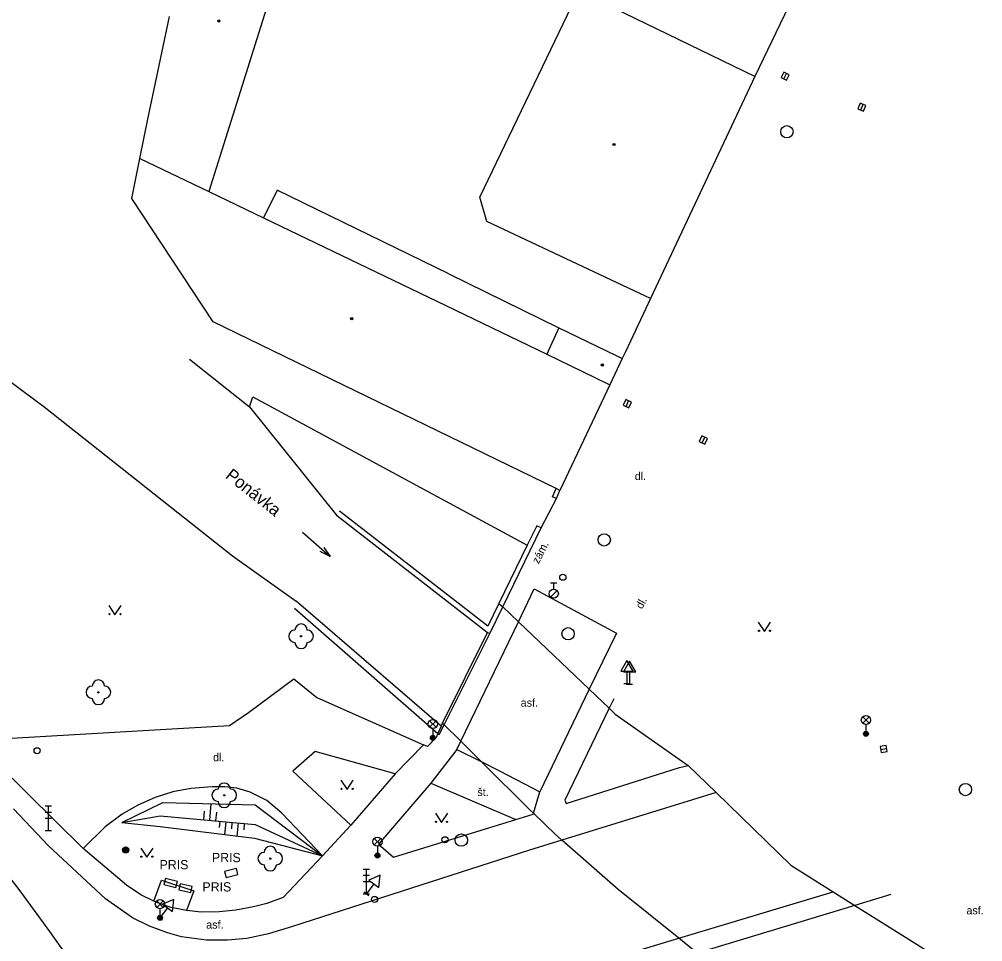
# Model space of a CAD drawing. Extents: x -598341 to -594502, y -1162301 to -1161406.
# Drawn here: x -597440.9 to -597362.6, y -1161701 to -1161626.1 of the extents above; entities that cross this region are included whole.
import ezdxf

# ---------------------------------------------------------------- set-up
doc = ezdxf.new("R2010")
doc.units = 0
for name, color, linetype in [('Vrstva 10', 7, 'Continuous'), ('Vrstva 11', 7, 'Continuous'), ('Vrstva 13', 7, 'Continuous'), ('Vrstva 14', 7, 'Continuous'), ('Vrstva 15', 7, 'Continuous'), ('Vrstva 22', 7, 'Continuous'), ('Vrstva 24', 7, 'Continuous'), ('Vrstva 25', 7, 'Continuous'), ('Vrstva 27', 7, 'Continuous'), ('Vrstva 28', 7, 'Continuous'), ('Vrstva 33', 7, 'Continuous'), ('Vrstva 34', 7, 'Continuous'), ('Vrstva 36', 7, 'Continuous'), ('Vrstva 39', 7, 'Continuous'), ('Vrstva 40', 7, 'Continuous'), ('Vrstva 41', 7, 'Continuous'), ('Vrstva 45', 7, 'Continuous'), ('Vrstva 5', 7, 'Continuous'), ('Vrstva 7', 7, 'Continuous'), ('Vrstva 8', 7, 'Continuous'), ('Vrstva 9', 7, 'Continuous')]:
    doc.layers.add(name, color=color, linetype=linetype)

msp = doc.modelspace()

# ---------------------------------------------------------------- linework, layer by layer
at = {"layer": 'Vrstva 10'}
for p, q in [((-597370.1, -1161697.18), (-597373.02, -1161698.07)), ((-597373.02, -1161698.07), (-597385.82, -1161701.94)), ((-597418.7, -1161699.79), (-597420.65, -1161700.39))]:
    msp.add_line(p, q, dxfattribs=at)
for points in [[(-597400.35, -1161675.03), (-597399.06, -1161672.36)], [(-597405.03, -1161684.74), (-597400.35, -1161675.03)], [(-597392.38, -1161675.96), (-597394.59, -1161680.52)], [(-597394.59, -1161680.52), (-597398.61, -1161688.85)], [(-597405.35, -1161685.4), (-597405.03, -1161684.74)], [(-597405.35, -1161685.4), (-597403.37, -1161686.39)], [(-597403.37, -1161686.39), (-597401.88, -1161687.13), (-597398.61, -1161688.85)], [(-597384.3, -1161688.91), (-597386.21, -1161689.5), (-597396.81, -1161692.78)], [(-597441.35, -1161690.23), (-597438.49, -1161693.23), (-597433.86, -1161697.55)], [(-597396.81, -1161692.78), (-597399.44, -1161693.59), (-597418.7, -1161699.79)], [(-597420.65, -1161700.39), (-597422.4, -1161700.77), (-597423.96, -1161700.91), (-597425.66, -1161700.91), (-597427.69, -1161700.63), (-597428.84, -1161700.31), (-597430.29, -1161699.77), (-597431.69, -1161699.07), (-597433.86, -1161697.55)], [(-597387.31, -1161700.74), (-597374.78, -1161696.97)], [(-597405.85, -1161708), (-597406.33, -1161706.48), (-597387.31, -1161700.74)]]:
    msp.add_lwpolyline(points, dxfattribs=at)
at = {"layer": 'Vrstva 11'}
for p, q in [((-597405.99, -1161646.77), (-597397.06, -1161651.14)), ((-597422.18, -1161657.58), (-597421.9, -1161656.76)), ((-597421.9, -1161656.76), (-597399.63, -1161668.81)), ((-597397.26, -1161665.03), (-597396.98, -1161664.36)), ((-597415.12, -1161666.36), (-597402.85, -1161675.89)), ((-597401.61, -1161673.83), (-597398.5, -1161667.41)), ((-597399.06, -1161672.36), (-597392.38, -1161675.96)), ((-597406.61, -1161683.5), (-597418.38, -1161673.35)), ((-597440.21, -1161688.98), (-597444.66, -1161684.59)), ((-597410.34, -1161687.39), (-597413.95, -1161691.56)), ((-597407.47, -1161688.13), (-597400.55, -1161691.1)), ((-597435.68, -1161693.45), (-597440.21, -1161688.98)), ((-597419.55, -1161690.59), (-597416.26, -1161694.05)), ((-597435.68, -1161693.45), (-597433.91, -1161691.68)), ((-597413.95, -1161691.56), (-597416.26, -1161694.05)), ((-597432.16, -1161696.43), (-597435.68, -1161693.45)), ((-597416.26, -1161694.05), (-597419.44, -1161697.43)), ((-597426.7, -1161696.9), (-597427.29, -1161698.5))]:
    msp.add_line(p, q, dxfattribs=at)
for points in [[(-597405.99, -1161646.77), (-597419.92, -1161639.96), (-597421.03, -1161642.23)], [(-597401.93, -1161673.54), (-597402.83, -1161675.4), (-597414.88, -1161666.04)], [(-597402.67, -1161675.99), (-597401.61, -1161673.83)], [(-597406.51, -1161683.28), (-597402.85, -1161675.89)], [(-597402.85, -1161675.89), (-597402.67, -1161675.99)], [(-597422.25, -1161682.39), (-597418.57, -1161679.66), (-597416.71, -1161681.18), (-597408.06, -1161685.03)], [(-597392.61, -1161681.3), (-597392.98, -1161682.06)], [(-597423.81, -1161683.45), (-597422.25, -1161682.39)], [(-597392.98, -1161682.06), (-597396.58, -1161689.53), (-597396.48, -1161689.79), (-597387.28, -1161686.86), (-597386.56, -1161686.72)], [(-597441.95, -1161684.52), (-597430.36, -1161683.83), (-597423.81, -1161683.45)], [(-597406.61, -1161683.5), (-597406.88, -1161684.1)], [(-597406.61, -1161683.5), (-597406.51, -1161683.28)], [(-597406.88, -1161684.1), (-597407.03, -1161684.44), (-597407.72, -1161685.16)], [(-597408.06, -1161685.03), (-597410.34, -1161687.39)], [(-597407.72, -1161685.16), (-597408.06, -1161685.03)], [(-597410.34, -1161687.39), (-597416.85, -1161685.57), (-597418.65, -1161687.16), (-597413.95, -1161691.56)], [(-597405.35, -1161685.4), (-597407.47, -1161688.13)], [(-597407.47, -1161688.13), (-597411.7, -1161693.09), (-597410.49, -1161694.16), (-597400.55, -1161691.1)], [(-597419.55, -1161690.59), (-597420.77, -1161689.56), (-597422.13, -1161688.88), (-597423.22, -1161688.56), (-597424.19, -1161688.44), (-597425.2, -1161688.45), (-597426.94, -1161688.58), (-597428.4, -1161688.86), (-597429.83, -1161689.32), (-597431.25, -1161689.92), (-597432.52, -1161690.65), (-597433.91, -1161691.68)], [(-597399.12, -1161690.59), (-597398.61, -1161688.85)], [(-597400.55, -1161691.1), (-597399.14, -1161690.67), (-597399.12, -1161690.59)], [(-597429.95, -1161697.73), (-597429.32, -1161696.01), (-597426.7, -1161696.9)], [(-597429.95, -1161697.73), (-597431, -1161697.21), (-597432.16, -1161696.43)], [(-597419.44, -1161697.43), (-597420.78, -1161697.92), (-597421.86, -1161698.2), (-597423.3, -1161698.47), (-597424.65, -1161698.6), (-597426.11, -1161698.61), (-597427.29, -1161698.5)], [(-597427.29, -1161698.5), (-597428.55, -1161698.24), (-597429.48, -1161697.92), (-597429.95, -1161697.73)]]:
    msp.add_lwpolyline(points, dxfattribs=at)
at = {"layer": 'Vrstva 13'}
msp.add_lwpolyline([(-597470.38, -1161668.8), (-597467.36, -1161670.94), (-597464.35, -1161673.04), (-597461.12, -1161675.62), (-597458.26, -1161678.06), (-597455.83, -1161680.23), (-597452.69, -1161683.22), (-597449.69, -1161686.37), (-597447.17, -1161689.18), (-597444.05, -1161692.84), (-597441, -1161696.66), (-597438.41, -1161700.18), (-597435.66, -1161704.08), (-597430.7, -1161711.73), (-597427.13, -1161717.6), (-597424.11, -1161722.82), (-597422.33, -1161726)], dxfattribs=at)
at = {"layer": 'Vrstva 14'}
for p, q in [((-597401.61, -1161673.83), (-597400.35, -1161675.03)), ((-597400.35, -1161675.03), (-597394.59, -1161680.52)), ((-597394.59, -1161680.52), (-597392.98, -1161682.06)), ((-597392.98, -1161682.06), (-597392.48, -1161682.53)), ((-597392.48, -1161682.53), (-597386.56, -1161686.72)), ((-597406.38, -1161683.41), (-597406.51, -1161683.28)), ((-597405.03, -1161684.74), (-597406.38, -1161683.41)), ((-597403.37, -1161686.39), (-597405.03, -1161684.74)), ((-597399.37, -1161690.35), (-597403.37, -1161686.39)), ((-597368.92, -1161700.64), (-597365, -1161703.1))]:
    msp.add_line(p, q, dxfattribs=at)
for points in [[(-597427.04, -1161653.7), (-597422.18, -1161657.58)], [(-597443.15, -1161654.38), (-597439.28, -1161657.25)], [(-597439.28, -1161657.25), (-597438.87, -1161657.55), (-597423.56, -1161669.67), (-597418.38, -1161673.35)], [(-597422.18, -1161657.58), (-597415.12, -1161666.36)], [(-597386.56, -1161686.72), (-597384.3, -1161688.91)], [(-597384.3, -1161688.91), (-597378.23, -1161694.8), (-597374.78, -1161696.97)], [(-597432.55, -1161691.35), (-597429.21, -1161689.71), (-597421.73, -1161689.9)], [(-597421.73, -1161689.9), (-597416.26, -1161694.05)], [(-597399.12, -1161690.59), (-597399.37, -1161690.35)], [(-597396.81, -1161692.78), (-597397.36, -1161692.29), (-597399.12, -1161690.59)], [(-597432.55, -1161691.35), (-597429.42, -1161690.79), (-597421.71, -1161691.5)], [(-597432.55, -1161691.35), (-597429.43, -1161691.66), (-597421.77, -1161692.62)], [(-597421.71, -1161691.5), (-597416.26, -1161694.05)], [(-597421.77, -1161692.62), (-597416.26, -1161694.05)], [(-597387.31, -1161700.74), (-597392.25, -1161696.79), (-597396.81, -1161692.78)], [(-597374.78, -1161696.97), (-597373.02, -1161698.07)], [(-597373.02, -1161698.07), (-597368.92, -1161700.64)], [(-597385.82, -1161701.94), (-597387.31, -1161700.74)]]:
    msp.add_lwpolyline(points, dxfattribs=at)
at = {"layer": 'Vrstva 15'}
for p, q in [((-597425.41, -1161691.16), (-597425.28, -1161689.81)), ((-597425.9, -1161691.11), (-597425.84, -1161690.42)), ((-597424.91, -1161691.2), (-597424.84, -1161690.51)), ((-597424.6, -1161691.23), (-597424.64, -1161691.74)), ((-597424.1, -1161691.28), (-597424.2, -1161692.32)), ((-597423.6, -1161691.33), (-597423.65, -1161691.85)), ((-597423.1, -1161691.37), (-597423.2, -1161692.44)), ((-597422.61, -1161691.42), (-597422.65, -1161691.94))]:
    msp.add_line(p, q, dxfattribs=at)
at = {"layer": 'Vrstva 22'}
for centre in [(-597417.99, -1161676.21), (-597434.45, -1161680.76), (-597424.23, -1161689.13), (-597420.49, -1161694.27)]:
    msp.add_circle(centre, 0.05, dxfattribs=at)
for centre, start, end in [((-597418.49, -1161676.21), 90, 270), ((-597417.99, -1161675.71), 0, 180), ((-597417.49, -1161676.21), 270, 90), ((-597417.99, -1161676.71), 180, 0), ((-597434.95, -1161680.76), 90, 270), ((-597434.45, -1161680.26), 0, 180), ((-597433.95, -1161680.76), 270, 90), ((-597434.45, -1161681.26), 180, 0), ((-597424.23, -1161688.63), 0, 180), ((-597424.73, -1161689.13), 90, 270), ((-597423.73, -1161689.13), 270, 90), ((-597424.23, -1161689.63), 180, 0), ((-597420.49, -1161693.77), 0, 180), ((-597420.99, -1161694.27), 90, 270), ((-597419.99, -1161694.27), 270, 90), ((-597420.49, -1161694.77), 180, 0)]:
    msp.add_arc(centre, 0.5, start, end, dxfattribs=at)
at = {"layer": 'Vrstva 24'}
for points in [[(-597424.078, -1161695.811), (-597423.113, -1161695.552), (-597423.242, -1161695.069), (-597424.208, -1161695.328)], [(-597429.125, -1161696.386), (-597428.153, -1161696.621), (-597428.036, -1161696.135), (-597429.008, -1161695.9)], [(-597427.925, -1161696.796), (-597426.953, -1161697.031), (-597426.836, -1161696.545), (-597427.808, -1161696.31)]]:
    msp.add_lwpolyline(points, close=True, dxfattribs=at)
at = {"layer": 'Vrstva 25'}
for radius in [0.25, 0.2, 0.15, 0.1, 0.05]:
    msp.add_circle((-597432.23, -1161693.56), radius, dxfattribs=at)
at = {"layer": 'Vrstva 27'}
for p, q in [((-597378.798, -1161630.935), (-597378.582, -1161630.485)), ((-597372.555, -1161633.451), (-597372.365, -1161632.989)), ((-597391.605, -1161657.547), (-597391.395, -1161657.093)), ((-597385.438, -1161660.486), (-597385.222, -1161660.034)), ((-597370.936, -1161685.412), (-597370.443, -1161685.328))]:
    msp.add_line(p, q, dxfattribs=at)
for points in [[(-597378.573, -1161631.044), (-597378.356, -1161630.593), (-597378.807, -1161630.376), (-597379.024, -1161630.827)], [(-597372.324, -1161633.547), (-597372.133, -1161633.084), (-597372.596, -1161632.893), (-597372.787, -1161633.356)], [(-597391.378, -1161657.652), (-597391.168, -1161657.198), (-597391.622, -1161656.988), (-597391.832, -1161657.442)], [(-597385.212, -1161660.593), (-597384.997, -1161660.142), (-597385.448, -1161659.927), (-597385.663, -1161660.378)], [(-597370.894, -1161685.659), (-597370.401, -1161685.575), (-597370.485, -1161685.082), (-597370.978, -1161685.166)]]:
    msp.add_lwpolyline(points, close=True, dxfattribs=at)
for centre in [(-597378.55, -1161635.22), (-597393.38, -1161668.38), (-597396.31, -1161676.01), (-597364.05, -1161688.66), (-597404.98, -1161692.77)]:
    msp.add_circle(centre, 0.5, dxfattribs=at)
at = {"layer": 'Vrstva 28'}
for p, q in [((-597397.738, -1161673.022), (-597397.208, -1161672.492)), ((-597397.73, -1161671.875), (-597397.23, -1161671.875)), ((-597397.48, -1161672.375), (-597397.48, -1161671.875))]:
    msp.add_line(p, q, dxfattribs=at)
for centre, radius in [((-597396.74, -1161671.41), 0.25), ((-597397.48, -1161672.75), 0.375), ((-597439.42, -1161685.51), 0.25), ((-597406.31, -1161692.74), 0.25), ((-597412.03, -1161697.59), 0.25)]:
    msp.add_circle(centre, radius, dxfattribs=at)
at = {"layer": 'Vrstva 33'}
for p, q in [((-597372.395, -1161683.28), (-597371.865, -1161682.75)), ((-597372.395, -1161682.75), (-597371.865, -1161683.28)), ((-597407.555, -1161683.6), (-597407.025, -1161683.07)), ((-597407.555, -1161683.07), (-597407.025, -1161683.6)), ((-597372.13, -1161683.39), (-597372.13, -1161684.14)), ((-597407.29, -1161683.71), (-597407.29, -1161684.46)), ((-597438.76, -1161689.99), (-597438.26, -1161689.99)), ((-597438.76, -1161690.49), (-597438.26, -1161690.49)), ((-597438.51, -1161691.99), (-597438.51, -1161689.99)), ((-597438.76, -1161690.99), (-597438.26, -1161690.99)), ((-597438.76, -1161691.99), (-597438.26, -1161691.99)), ((-597412.055, -1161693.16), (-597411.525, -1161692.63)), ((-597412.055, -1161692.63), (-597411.525, -1161693.16)), ((-597411.79, -1161693.27), (-597411.79, -1161694.02)), ((-597412.94, -1161695.13), (-597412.44, -1161695.13)), ((-597412.69, -1161697.13), (-597412.69, -1161695.13)), ((-597412.94, -1161695.63), (-597412.44, -1161695.63)), ((-597412.94, -1161696.13), (-597412.44, -1161696.13)), ((-597412.94, -1161697.13), (-597412.44, -1161697.13)), ((-597429.715, -1161698.23), (-597429.185, -1161697.7)), ((-597429.715, -1161697.7), (-597429.185, -1161698.23)), ((-597429.45, -1161698.34), (-597429.45, -1161699.09))]:
    msp.add_line(p, q, dxfattribs=at)
for centre, radius in [((-597372.13, -1161683.015), 0.375), ((-597407.29, -1161683.335), 0.375), ((-597407.29, -1161684.46), 0.2), ((-597407.29, -1161684.46), 0.145), ((-597372.13, -1161684.14), 0.2), ((-597372.13, -1161684.14), 0.145), ((-597372.13, -1161684.14), 0.0876), ((-597407.29, -1161684.46), 0.0876), ((-597411.79, -1161692.895), 0.375), ((-597411.79, -1161694.02), 0.2), ((-597411.79, -1161694.02), 0.145), ((-597411.79, -1161694.02), 0.0876), ((-597429.45, -1161697.965), 0.375), ((-597429.45, -1161699.09), 0.2), ((-597429.45, -1161699.09), 0.145), ((-597429.45, -1161699.09), 0.0876)]:
    msp.add_circle(centre, radius, dxfattribs=at)
at = {"layer": 'Vrstva 34'}
for p, q in [((-597391.54, -1161679.032), (-597391.54, -1161680.05)), ((-597391.32, -1161679.092), (-597391.32, -1161680.11)), ((-597391.79, -1161680.05), (-597391.29, -1161680.05)), ((-597391.57, -1161680.11), (-597391.07, -1161680.11)), ((-597412.078, -1161696.317), (-597412.69, -1161697.13)), ((-597412.89, -1161696.98), (-597412.49, -1161697.28)), ((-597428.838, -1161698.277), (-597429.45, -1161699.09)), ((-597429.65, -1161698.94), (-597429.25, -1161699.24))]:
    msp.add_line(p, q, dxfattribs=at)
for points in [[(-597392.04, -1161679.032), (-597391.04, -1161679.032), (-597391.54, -1161678.166)], [(-597391.82, -1161679.092), (-597390.82, -1161679.092), (-597391.32, -1161678.226)], [(-597412.477, -1161696.016), (-597411.678, -1161696.617), (-597411.557, -1161695.625)], [(-597429.237, -1161697.976), (-597428.438, -1161698.577), (-597428.317, -1161697.585)]]:
    msp.add_lwpolyline(points, close=True, dxfattribs=at)
at = {"layer": 'Vrstva 36'}
for points in [[(-597433.6, -1161673.71), (-597433.1, -1161674.46), (-597432.6, -1161673.71)], [(-597380.87, -1161675.06), (-597380.37, -1161675.81), (-597379.87, -1161675.06)], [(-597414.76, -1161687.9), (-597414.26, -1161688.65), (-597413.76, -1161687.9)], [(-597407.09, -1161690.58), (-597406.59, -1161691.33), (-597406.09, -1161690.58)], [(-597431.01, -1161693.41), (-597430.51, -1161694.16), (-597430.01, -1161693.41)]]:
    msp.add_lwpolyline(points, dxfattribs=at)
for centre in [(-597433.55, -1161674.41), (-597432.651, -1161674.41), (-597380.82, -1161675.76), (-597379.921, -1161675.76), (-597414.71, -1161688.6), (-597413.811, -1161688.6), (-597407.04, -1161691.28), (-597406.141, -1161691.28), (-597430.96, -1161694.11), (-597430.061, -1161694.11)]:
    msp.add_circle(centre, 0.05, dxfattribs=at)
at = {"layer": 'Vrstva 39'}
for centre, radius in [((-597424.67, -1161626.22), 0.09), ((-597424.67, -1161626.22), 0.0398), ((-597392.59, -1161636.26), 0.09), ((-597392.59, -1161636.26), 0.0398), ((-597413.88, -1161650.41), 0.09), ((-597413.88, -1161650.41), 0.0398), ((-597393.53, -1161654.17), 0.09), ((-597393.53, -1161654.17), 0.0398)]:
    msp.add_circle(centre, radius, dxfattribs=at)
at = {"layer": 'Vrstva 45'}
msp.add_line((-597417.886, -1161667.762), (-597415.63, -1161669.74), dxfattribs=at)
msp.add_lwpolyline([(-597416.137, -1161668.988), (-597415.63, -1161669.74), (-597416.44, -1161669.335)], dxfattribs=at)
at = {"layer": 'Vrstva 5'}
for p, q in [((-597365.81, -1161598.67), (-597381.15, -1161630.74)), ((-597419.32, -1161620.49), (-597425.49, -1161640.09)), ((-597403.47, -1161640.54), (-597395.44, -1161623.79)), ((-597381.15, -1161630.74), (-597395.44, -1161623.79)), ((-597430.43, -1161634.2), (-597428.68, -1161625.87)), ((-597381.15, -1161630.74), (-597389.62, -1161648.77)), ((-597431.07, -1161637.4), (-597430.43, -1161634.2)), ((-597431.73, -1161640.64), (-597431.07, -1161637.4)), ((-597431.07, -1161637.4), (-597425.49, -1161640.09)), ((-597425.49, -1161640.09), (-597421.03, -1161642.23)), ((-597425.14, -1161650.67), (-597431.73, -1161640.64)), ((-597402.92, -1161642.51), (-597403.47, -1161640.54)), ((-597421.03, -1161642.23), (-597406.97, -1161648.99)), ((-597390.07, -1161648.54), (-597402.92, -1161642.51)), ((-597406.97, -1161648.99), (-597398.03, -1161653.3)), ((-597389.62, -1161648.77), (-597390.07, -1161648.54)), ((-597397.29, -1161664.21), (-597425.14, -1161650.67)), ((-597397.06, -1161651.14), (-597398.03, -1161653.3)), ((-597397.06, -1161651.14), (-597392.41, -1161653.41)), ((-597398.03, -1161653.3), (-597395.14, -1161654.69)), ((-597391.92, -1161653.65), (-597392.93, -1161655.79)), ((-597392.41, -1161653.41), (-597391.92, -1161653.65)), ((-597395.14, -1161654.69), (-597392.93, -1161655.79)), ((-597392.93, -1161655.79), (-597396.98, -1161664.36)), ((-597396.98, -1161664.36), (-597397.29, -1161664.21))]:
    msp.add_line(p, q, dxfattribs=at)
at = {"layer": 'Vrstva 7'}
for points in [[(-597389.62, -1161648.77), (-597391.66, -1161653.09), (-597391.92, -1161653.65)], [(-597397.26, -1161665.03), (-597397.57, -1161664.88), (-597397.29, -1161664.21)], [(-597398.5, -1161667.41), (-597398.86, -1161667.24), (-597399.63, -1161668.81)], [(-597399.63, -1161668.81), (-597401.93, -1161673.54)], [(-597401.93, -1161673.54), (-597401.61, -1161673.83)]]:
    msp.add_lwpolyline(points, dxfattribs=at)
at = {"layer": 'Vrstva 8'}
msp.add_line((-597398.5, -1161667.41), (-597397.26, -1161665.03), dxfattribs=at)
at = {"layer": 'Vrstva 9'}
for points in [[(-597418.53, -1161673.92), (-597406.88, -1161684.1)], [(-597406.38, -1161683.41), (-597402.67, -1161675.99)], [(-597406.88, -1161684.1), (-597406.77, -1161684.19), (-597406.38, -1161683.41)]]:
    msp.add_lwpolyline(points, dxfattribs=at)

# ---------------------------------------------------------------- texts
at = {"layer": 'Vrstva 40'}
for s, p in [('dl.', (-597390.9, -1161663.52)), ('asf.', (-597400.16, -1161681.93)), ('dl.', (-597425.13, -1161686.36)), ('št.', (-597403.68, -1161689.19)), ('asf.', (-597363.97, -1161698.8)), ('asf.', (-597425.69, -1161699.96))]:
    msp.add_text(s, height=0.65, dxfattribs=at).set_placement(p)
for s, height, rotation, p in [('zám.', 0.65, 63.14053, (-597398.71, -1161670.38)), ('dl.', 0.6499, 61.40031, (-597390.31, -1161674.05))]:
    msp.add_text(s, height=height, rotation=rotation, dxfattribs=at).set_placement(p)
at = {"layer": 'Vrstva 41'}
for p in [(-597429.48, -1161695.14), (-597425.23, -1161694.56), (-597426, -1161696.94)]:
    msp.add_text('PRIS', height=0.75, dxfattribs=at).set_placement(p)
at = {"layer": 'Vrstva 45'}
msp.add_text('Ponávka', height=0.9999, rotation=321.64124, dxfattribs=at).set_placement((-597424.2, -1161663.29))

doc.saveas('drawing.dxf')
